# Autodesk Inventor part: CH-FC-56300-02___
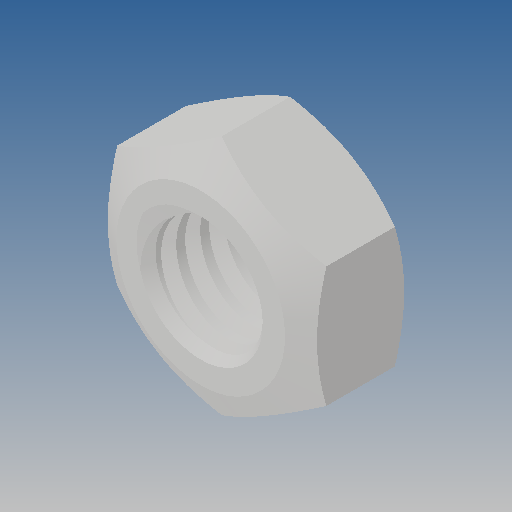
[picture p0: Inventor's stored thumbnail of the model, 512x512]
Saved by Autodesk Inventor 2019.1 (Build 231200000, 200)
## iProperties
Created: 2012-09
Part Number: CH-FC-56300-02___
Material: Ogólny
Document SubType Name: Modeling
Designer: CADENGINEERING4
Density: 1 g/cm^3
Appearance: Domyślna
Author: CADENGINEERING4
Revision Number: ÈÎºÎ
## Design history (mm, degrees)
feature "NONE"
node "Bryła1"
